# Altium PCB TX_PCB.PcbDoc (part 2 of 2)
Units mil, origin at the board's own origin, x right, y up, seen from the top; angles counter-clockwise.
Board outline 2335 x 2060 mil, 2 copper layers (Top Layer, Bottom Layer); 122 components, 95 nets, 483 pads, 219 vias.
Unrouted connection lines stored in the file: 1.
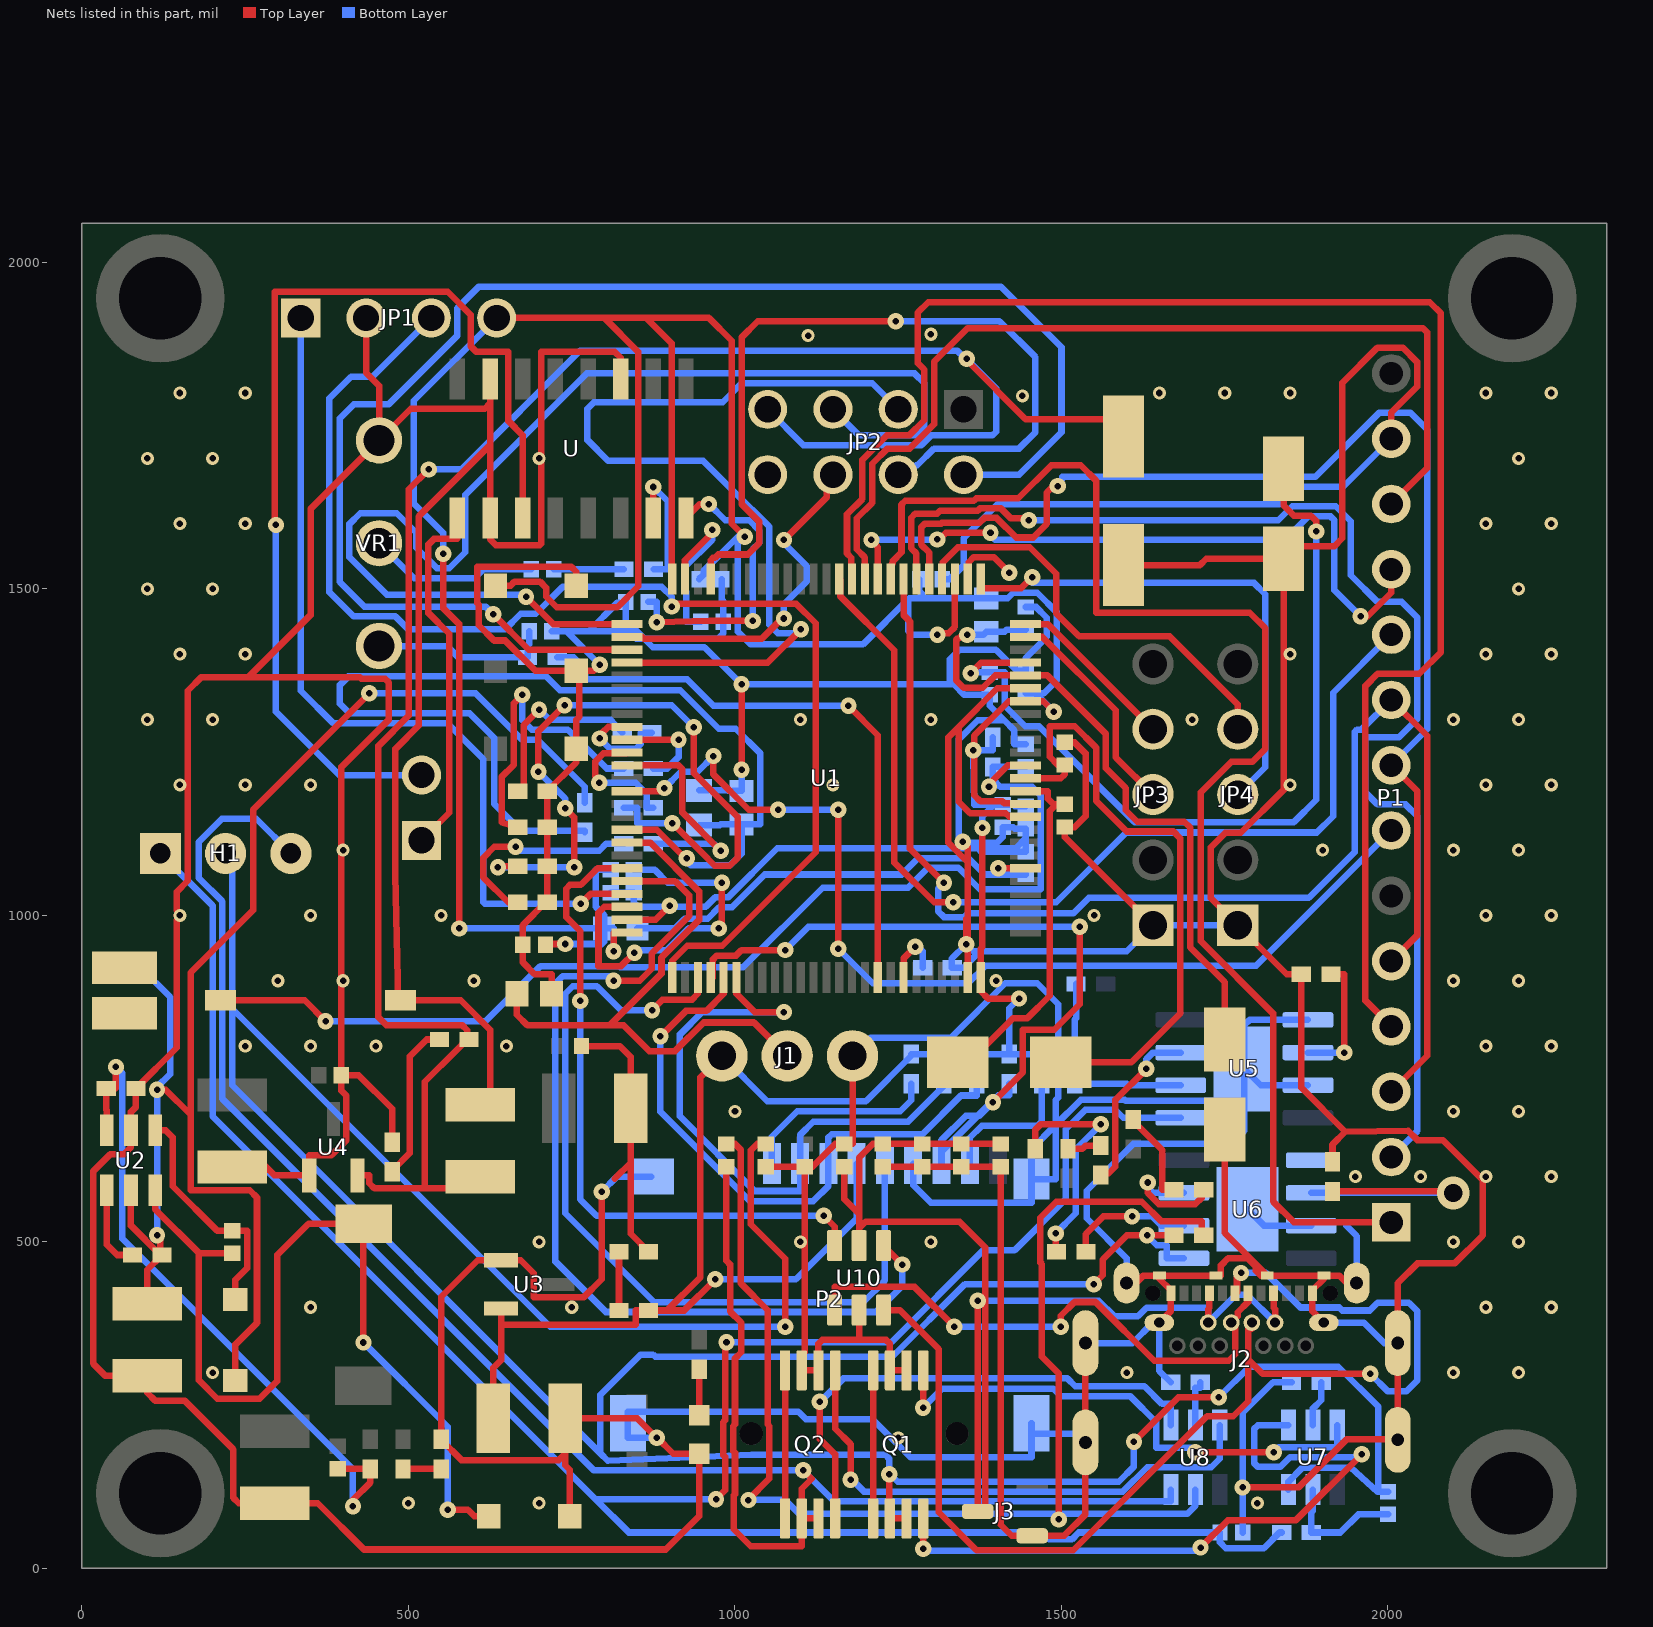
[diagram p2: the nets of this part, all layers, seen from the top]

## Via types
v1: diameter 25, hole 10, Top Layer to Bottom Layer, 130 vias
v2: diameter 20, hole 10, Top Layer to Bottom Layer, 86 vias
v3: diameter 70.87, hole 59.06, Top Layer to Bottom Layer, 2 vias
v4: diameter 50, hole 28, Top Layer to Bottom Layer, 1 vias

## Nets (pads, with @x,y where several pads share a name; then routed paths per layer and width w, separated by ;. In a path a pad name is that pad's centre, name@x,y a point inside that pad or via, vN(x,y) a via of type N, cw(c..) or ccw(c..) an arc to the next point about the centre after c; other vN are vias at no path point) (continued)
+5_USB_A: C34.1 C35.1 C36.1 C37.1 C42.2 J2.A4 J2.A9 J2.B4 J2.B9 J3.3 U10.5 | length 2013.9
  Top Layer w10: C42.2@1167.36,615.35 1167.36,565.64 1190,543 ; U10.5@1190,494.41 1190,521 ; J3.3@1371.54,87.4 J3.3@1372,87.4 ; v1(1372,410) J3.3@1372,87.4 ; C37.1@1407.09,650 C36.1@1346.81,650 C34.1@1286.54,650 C35.1@1226.26,650 1211,650 1190,629 1190,543 ; J2.B9@1724.65,376.5 1724.65,397 1726.61,398.97 J2.A4@1726.61,421.38 ; J2.A9@1825.04,421.38 1825.04,398.97 1827.01,397 J2.B4@1827.01,376.5 ; 1190,521 1190,543 ; 1190,521 1200,531 1344,531 1383,492 1383,87.4 J3.3@1372,87.4
  Bottom Layer w10: v1(1372,410) 1557,410 1581,386 1617,386 1630.29,399.29 1724.65,399.29 J2.B9@1724.65,376.5 1767.15,419 1784.5,419 J2.B4@1827.01,376.5
+8.4: C21.2 D1.1 pad.9 R7.2 R20.2 U2.5 | length 2453.6
  Top Layer w10: U2.5@75,579 75,525 R20.2@120,480 ; C21.2@100,405.12 100,457.36 R20.2@122.64,480 R20.2@120,480 ; v1(115,510) 120,505 R20.2@120,480 ; v1(115,733) 128,733 166.42,694.58 ; D1.1@235,287.99 235,343 268,376 268,568 257,579 166.42,579 166.42,694.58 ; v1(440,1340) 262,1162 262,1008 166.42,912.42 166.42,694.58
  Bottom Layer w10: pad.9@65,920 90,920 135,875 135,757.06 115,737.06 v1(115,510) ; v1(440,1340) 603.03,1340 674.03,1269 698,1269 770,1197 R7.2@770,1172.64
ADC_Pin: C29.2 R7.1 R15.2 U1.67 | length 1700.5
  Top Layer w10: U1.67@834.88,1131.26 880.11,1131.26 923.87,1087.5 v1(926.04,1087.5)
  Bottom Layer w10: R7.1@770,1127.36 770,1130 672,1130 631,1171 631,1272 593.44,1309.56 409.57,1309.56 395,1324.13 395,1353 408,1366 711,1366 732,1345 916,1345 975,1286 1001,1286 1039,1248 1039,1139.41 R15.2@1010,1139.41 ; v1(926.04,1087.5) 926.04,1082.72 931.9,1076.86 931.9,1076.5 992,1076.5 1010,1094.5 R15.2@1010,1139.41 ; C29.2@945,1138.43 977,1138.43 977.98,1139.41 R15.2@1010,1139.41
ADC_VR_ESC: C24.2 J1.2 U1.68 | length 911.5
  Top Layer w10: C24.2@665.92,880 665.92,848 682.42,831.5 808,831.5 ; U1.68@834.88,1111.58 870.14,1111.58 945,1036.72 945,992.96 887.48,935.44 887.48,910.98 808,831.5 ; J1.2@1080,785 1029,836 952.07,836 908.33,792.26 868.74,792.26 829.5,831.5 808,831.5
Audio_PWM: R8.2 U1.92 | length 920.6
  Top Layer w10: v1(1173.74,1321) 1218.74,1276 U1.92@1218.74,904.88
  Bottom Layer w10: R8.2@727.64,1395 753,1395 771,1377 771,1361.5 926.5,1361.5 967,1321 v1(1173.74,1321)
B+: C38.1 H1.1 R27.2 U5.5 | length 3719.2
  Top Layer w10: v1(971,106) 985,120 985,170.68 982.21,173.47 982.21,224.15 985,226.95 985,344.5 v1(987,346.5)
  Bottom Layer w10: H1.1@120,1095 200,1015 200,692.5 786.5,106 ; v1(971,106) 786.5,106 ; v1(987,346.5) 1239.5,346.5 1380,487 1428,487 1506.59,565.59 1506.59,672.48 1536.62,702.5 1582,702.5 1594.5,690 U5.5@1682.56,690 ; R27.2@1837.36,55 1834,55 1810,31 1751.68,31 1742.68,40 C38.1@1742.68,55 1526.5,55 1516,44.5 1481.5,44.5 1471,55 837.5,55 786.5,106
B-: C41.2 H1.3 Q2.2 Q2.3 U8.6 | length 3153.6
  Top Layer w10: C41.2@986.54,615.35 986.54,471.46 992.5,465.5 992.5,393.5 1009.5,376.5 1009.5,331 1000,321.5 1000,220.73 997.21,217.94 997.21,179.69 1000,176.89 1000,113.79 998.1,111.89 998.1,59.9 1024,34 1102.2,34 Q2.2@1102.2,76.61 ; v1(1104.3,150.5) 1117.5,137.3 1102.2,122 Q2.2@1102.2,76.61 ; Q2.3@1127.8,76.61 Q2.2@1102.2,76.61
  Bottom Layer w10: H1.3@320,1095 267,1148 214.32,1148 178.5,1112.19 178.5,1057.71 215,1021.21 215,719 784,150 1031.5,150 1032,150.5 v1(1104.3,150.5) 1152.16,102.64 1667.64,102.64 U8.6@1667.64,120.59
B_COM: C39.2 C40.1 H1.2 Q1.2 Q1.3 R31.2 U6.5 U7.6 | length 5453
  Top Layer w10: C40.1@1046.81,650 1034.21,650 1024.21,640 1024.21,527 1077,474.21 v1(1077,370) ; v1(1236,144) 1236,77.82 Q1.2@1237.2,76.61 Q1.3@1262.8,76.61 ; v1(1549.39,435.39) 1563,449 1563,473 1600,510 v1(1631,510) R31.2@1672.36,510 ; v1(1611,194) 1679,262 v1(1741,262)
  Bottom Layer w10: H1.2@220,1095 230,1085 230,857 ; v1(1077,370) 717,370 230,857 ; v1(1549.39,435.39) 1352.39,435.39 1241,324 877.82,324 874.32,327.5 855.68,327.5 794,265.82 794,176 ; v1(1611,194) 1611,156 1587.64,132.64 1249.36,132.64 1237.99,144 v1(1236,144) 1236,168.14 1230.14,174 1035,174 1025.5,174 805,165 794,176 ; v1(1631,510) 1646,495 1661,495 1661,475 U6.5@1687.56,475 ; v1(1741,262) 1788,309 1924,309 1985.32,247.69 1985.32,118.14 1984.5,117.32 ; U7.6@1847.6,120.59 1847.6,132.79 1869.21,154.41 1938.16,154.41 1943.1,154.31 1984.5,117.32 ; C39.2@2000,117.32 1984.5,117.32 ; 230,857 230,740 794,176
BOOT0: R6.2 U1.94 | length 93.8
  Top Layer w10: U1.94@1258.11,904.88 1258.11,934.11 v1(1276.18,952.18)
  Bottom Layer w10: v1(1276.18,952.18) 1280,952.18 1287.36,944.82 R6.2@1287.36,920
CHRG_LED: R28.1 U5.7 | length 270.7
  Top Layer w10: R28.1@1560,602.36 1560,605 1572.5,605 1582.5,615 1582.5,717.5 v1(1630,765)
  Bottom Layer w10: v1(1630,765) 1630,780 1640,790 U5.7@1682.56,790
CHRG_LED_1: R32.1 U6.7 | length 191.7
  Top Layer w10: v1(1632,591) 1632,575 1649,558 1705,558 1715,568 1715,580 R32.1@1717.64,580
  Bottom Layer w10: v1(1632,591) 1632,583 1640,575 U6.7@1687.56,575
CLK_SD: P2.5 U1.78 | length 1333
  Top Layer w10: v1(873,855) 889,871 934.15,871 943.15,880 U1.78@943.15,904.88
  Bottom Layer w10: v1(873,855) 825,855 788.5,891.5 751.5,891.5 740,880 740,544 876.31,407.69 1196.33,407.69 1229.65,441 P2.5@1229.65,619.84
CS_SD: P2.2 R18.1 U1.81 | length 980.2
  Top Layer w10: U1.81@1002.2,904.88 1002.2,880 1030.2,852 v1(1075,852)
  Bottom Layer w10: v1(1075,852) 950,852 915.63,817.63 915.63,692.37 1030,578 1099.72,578 P2.2@1099.72,619.84 1099.72,663.72 1120,684 1265,684 1320,739 R18.1@1320,742.36
DISPL_CS: P1.12 U1.35 | length 1471.8
  Top Layer w10: U1.35@1199.06,1515.12 1199.06,1548.06 1186.51,1560.6 1186.51,1608.07 1210.08,1631.64 1210.08,1691.54 1233.54,1715 1267.67,1715 1304.92,1752.25 1304.92,1847.92 1356.53,1899.53 2053.21,1899.53 2060,1892.74 2060,1685 P1.12@2005,1630
DISPL_DC: P1.10 U1.37 | length 1535.9
  Top Layer w10: U1.37@1159.69,1515.12 1160.99,1513.82 1160.99,1489.01 1244,1406 1244,1081 1305,1020 v1(1334,1020)
  Bottom Layer w10: v1(1334,1020) 1492,1020 1599,1127 1891,1127 1916,1152 1916,1341 P1.10@2005,1430
DISPL_LED: P1.7 U1.64 | length 1574.6
  Top Layer w10: U1.64@834.88,1190.32 887.32,1190.32 v1(892,1195) ; v1(967,1244) 967,1216 1021,1162 v1(1066,1162) ; v1(1158,949) v1(1158,1162)
  Bottom Layer w10: v1(892,1195) 917,1220 943,1220 v1(967,1244) ; v1(1066,1162) v1(1158,1162) ; v1(1158,949) 1211,896 1357,896 1384,923 1798,923 P1.7@2005,1130
DISPL_MOSI: P1.3 P1.9 U1.32 | length 2126.7
  Top Layer w10: U1.32@1258.11,1515.12 1258.11,1459.89 1268,1450 1268,1102 v1(1320,1050) ; P1.3@2005,730 2060,785 2060,1275 P1.9@2005,1330
  Bottom Layer w10: v1(1320,1050) 1311,1041 1311,1006.5 1320,997.5 1351.5,997.5 1357,1003 1518,1003 1542,1027 1879,1027 1949,1097 1949,1280.91 1952.62,1284.53 1959.53,1284.53 P1.9@2005,1330
DISPL_RST: P1.11 U1.34 | length 1055.6
  Top Layer w10: v1@1209.01,1569.92 1212.88,1569.92 1218.74,1564.06 U1.34@1218.74,1515.12 ; v1(1309.69,1575.72) 1312.68,1575.72 1323.05,1586.09 1337.26,1586.09 1337.41,1586.24 v1(1391.27,1586.24) ; v1(1958,1458) 1969,1458 2005,1494 P1.11@2005,1530
  Bottom Layer w10: v1@1214.09,1575 1214.45,1575.36 1309.33,1575.36 v1(1309.69,1575.72) ; v1(1391.27,1586.24) 1391.27,1582.18 1398.45,1575 1842,1575 1878,1611 1912,1611 1918,1605 1918,1498 v1(1958,1458)
  other v1: 1209.01,1575
DISPL_SCK: P1.5 P1.8 U1.30 | length 1869.7
  Top Layer w10: U1.30@1297.48,1515.12 1297.48,1555.7 1285,1568.18 1285,1594.14 1290.86,1600 1315.75,1600 1316.99,1601.24 1374.45,1601.24 1381.95,1608.74 1400.58,1608.74 1430.58,1578.74 1456.77,1578.74 1477.5,1599.47 1477.5,1647.5 1487.5,1657.5 v1(1494.32,1657.5) ; P1.5@2005,930 2045,970 2045,1190 P1.8@2005,1230
  Bottom Layer w10: v1(1494.32,1657.5) 1494.32,1661.56 1501.5,1668.74 1501.5,1671.5 1888.5,1671.5 1987,1770 2034,1770 2060,1744 2060,1285 P1.8@2005,1230
GND: C1.1 C2.1 C3.1 C4.1 C5.1 C6.1 C7.2 C8.1 C9.1 C10.1 C11.1 C12.1 C13.1 C14.1 C15.1 C17.1 C18.1 C21.1 C22.1 C23.1 C24.1 C25.2 C26.1 C27.2 C28.1 C29.1 C30.2 C31.1 C32.1 C33.1 C34.2 C35.2 C36.2 C37.2 C38.2 C40.2 C42.1 C43.2 D2.1 D3.2 D4.1 D5.2 D8.1 D9.1 D10.2 D11.2 D12.2 D13.2 D14.2 D15.2 J1.1 J2.A1 J2.A12 J2.B1 J2.B12 J2.S J3.1 JP1.2 JP2.5 JP3.1 JP4.1 P1.13 P2.6 P2.G1 P2.G2 P2.G3 P2.G4 pad.10 Q1.6 Q1.7 Q2.6 Q2.7 R6.1 R10.1 R15.1 R22.1 R25.1 R26.2 R30.2 S2.1 U1.10 U1.20 U1.27 U1.74 U1.99 U2.2 U3.1 U4.1 U5.1 U5.3 U5.9 U6.1 U6.3 U6.9 U10.2 U.2 U.11 U.15 VR1.2 | length 25006.7
  Top Layer w10: C31.1@230,614.76 282,614.76 294.76,602 U4.1@348,602 348,633 382,633 405,656 405,724 397.32,731.68 C32.1@397.32,755 ; v2@397.32,900 C32.1@397.32,755 ; JP1.2@435,1915 435,1831 455,1811 VR1.2@455,1727.48 ; D15.2@475,652.64 475,704 424,755 C32.1@397.32,755 ; C33.1@610,710.12 625,725.12 625,825 580,870 S2.1@487.8,870 484,870 480,1062 480,1255 515.5,1290.5 515.5,1610.77 625,1720.27 ; U.15@625,1821.3 625,1784 ; C24.1@719.07,877.93 C24.1@719.07,880 719.07,910 693.18,910 675.18,928 C13.1@675.18,955 675.18,985.18 710,1020 D13.2@712.64,1020 D12.2@712.64,1075 D11.2@712.64,1135 D10.2@712.64,1190 757.01,1234.37 D9.1@757.01,1255 757.01,1299.5 761.5,1303.99 761.5,1361.3 757.01,1361.3 D8.1@757.01,1375 ; D2.1@747.01,80 747.01,151 740.12,157.89 740.12,176 ; D4.1@757.01,1505 757.01,1526.2 749.5,1533.7 605.27,1533.7 605.27,1478.23 607.5,1476 607.5,1444.5 631,1421 648,1421 694,1375 D8.1@757.01,1375 ; C26.1@765,800 823.47,800 840.24,783.24 C23.1@840.24,705 840.24,621.24 ; v1(793,1384) 784,1375 D8.1@757.01,1375 ; v1(796,577) 796,443 768,415 692,415 692,452 672,472 U3.1@642,472 606,472 550,416 D3.2@550,197.64 550,197 581,166 730.12,166 740.12,176 ; 816,597 840.24,621.24 ; U.11@825,1821.3 825,1854 816,1863 703,1863 703,1569 701,1567 634,1567 625,1576 U.2@625,1608.7 625,1720.27 ; U1.74@834.88,993.47 878.47,993.47 v1(900,1015) ; D14.2@867.64,485 840.24,512.4 840.24,621.24 ; v1(880,200) 850,230 C28.1@740.12,230 740.12,176 ; v1@880.5,200.5 905.53,175.47 D5.2@945,175.47 945,80 894,29 431.88,29 361,99.88 C22.1@295,99.88 240,99.88 232,107.88 232,182 157,257 112,257 100,269 C21.1@100,294.88 36,294.88 17,313.88 17,608 43,634 64,634 75,645 U2.2@75,671 75,699 82.64,706.64 R22.1@82.64,735 145,797.36 145,992.29 148.09,995.38 148.09,997.29 145.38,1000 148.09,1002.71 148.09,1004.62 145,1007.71 145,1036 162,1053 162,1344 183,1365 255,1365 ; v1(1010,1223) v1(1010,1354) ; C40.2@1046.81,615.35 C43.2@1107,615.35 ; J1.1@1180,785 1180,650 C42.1@1167.36,650 1153.65,650 1119,615.35 C43.2@1107.09,615.35 C43.2@1107,615.35 ; U10.2@1190,395.59 1190,350 1189.84,349.84 ; C35.2@1226.26,615.36 C34.2@1286.54,615.36 C36.2@1346.81,615.36 C37.2@1407.09,615.36 1407.09,66.91 1424,50 J3.1@1455,50 1504,50 1536.65,82.65 J2.S@1536.65,193.03 J2.S@1536.65,345 ; Q1.6@1262.8,303.39 Q1.7@1237.2,303.39 1237.2,343.99 1231.35,349.84 1189.84,349.84 ; v1(1349,1113) 1356.5,1105.5 1356.5,1081.6 ; U1.99@1356.54,904.88 v1@1356.54,953.46 ; U1.27@1356.54,1515.12 1357.84,1516.42 1357.84,1540.8 1365.78,1548.74 1396.26,1548.74 v1(1420,1525) ; U1.10@1445.12,1150.95 1420.05,1150.95 1414.43,1156.57 1360,1156.57 1342.5,1174.07 1342.5,1288.5 ; U1.20@1445.12,1347.8 1401.8,1347.8 1342.5,1288.5 ; C4.1@1505,1265 1520,1265 1536.9,1248.1 1536.9,1152 1520.26,1135.35 C5.1@1505,1135.35 1505,1120 JP3.1@1640,985 ; C25.2@1595,1536.57 1712,1536.57 1721.53,1546.1 C30.2@1840,1546.1 ; J2.S@1599.65,437.13 1614.13,437.13 1625.54,448.54 J2.S@1649.84,448.54 ; J2.B12@1649.84,376.5 1667.56,394.21 J2.A1@1667.56,421.38 1667.56,426 1649.84,443.72 J2.S@1649.84,448.54 ; C27.2@1750,672.2 1750,513.74 J2.S@1815.2,448.54 ; v1(1777.32,124) 1863,124 1936.5,197.5 2014.47,197.5 J2.S@2015,196.97 J2.S@2015,345 2015,437 2045,467 2102,467 2145,510 2145,595 2084,656 2045,656 2031,670 1934.68,668.68 ; J2.B1@1901.81,376.5 1884.09,394.21 J2.A12@1884.09,421.38 1884.09,426 1901.81,443.72 J2.S@1901.81,448.54 ; R10.1@1915,622.64 1915,649 1934.68,668.68 ; J2.S@1952.01,437.13 1936.87,437.13 1925.46,448.54 J2.S@1901.81,448.54 ; P1.13@2005,1730 2005,1770 2044.53,1809.53 2044.53,1847.66 2022.66,1869.53 1984,1869.53 1930,1815.53 1930,1577.5 1918,1565.5 1840,1565.5 C30.2@1840,1546.1 ; 255,1365 350,1460 350,1622.48 VR1.2@455,1727.48 ; 255,1365 425,1365 427.5,1362.5 464.14,1362.5 470,1356.64 470,1300 397.32,1227.32 C32.1@397.32,755 ; VR1.2@455,1727.48 503.52,1776 617,1776 625,1784 ; 625,1720.27 625,1784 ; C43.2@1107,615.35 1107,330.8 1102.2,326 Q2.7@1102.2,303.39 Q2.6@1127.8,303.39 1127.8,343.99 1133.65,349.84 1189.84,349.84 ; 1342.5,1288.5 1326.54,1272.54 1326.54,1111.57 1356.5,1081.6 ; 1356.5,1081.6 1356.5,997.5 1354,995 v1(1354,956) v1@1356.54,953.46 ; 1356.5,1081.6 1356.54,1081.57 v1@1356.54,953.46 ; J2.S@1649.84,448.54 J2.S@1736.46,448.54 1744.15,448.54 1744.15,464 1755.15,475 1784.32,475 1797.5,461.82 1797.5,456 1804.96,448.54 J2.S@1815.2,448.54 ; J2.S@1815.2,448.54 J2.S@1901.81,448.54 ; C30.2@1840,1546.1 1840,1192 1774.5,1126.5 1751,1126.5 1728.5,1104 1728.5,1026.5 JP4.1@1770,985 1845,910 R25.1@1867.36,910 1867.36,736 1934.68,668.68
  Bottom Layer w10: C17.1@719.64,1435 742,1435 ; v1(793,1384) 742,1435 ; v1(796,577) 819.16,600.16 P2.G4@871.38,600.16 ; C11.1@810,1035 C2.1@845,1035 845,1020 851.5,1013.5 955.47,1013.5 969.47,1027.5 989.32,1027.5 1064.7,1102.88 1358.12,1102.88 ; C18.1@832.68,1480 C18.1@832.68,1479 ; v1(880,200) 835.94,200 P2.G3@835.94,222.21 835.94,240 1097.13,240 1108.39,228.74 1210.26,228.74 1269,170 1454.06,170 P2.G2@1454.06,206 ; C29.1@945,1191.57 988.97,1191.57 989.95,1190.59 R15.1@1010,1190.59 v1(1010,1223) ; C8.1@979.65,1515 979.65,1483.68 982.32,1481 C1.1@982.32,1450 982.32,1432 974.32,1424 861,1424 ; J1.1@1180,785 1208,813 1331,813 1414,896 1463,896 1495,864 1495,721 1491,717 1491,679 ; P2.6@1272.95,619.84 1272.95,587.05 1300,560 1454.06,560 P2.G1@1454.06,596.22 ; C14.1@1317.17,1515.12 1329.12,1515.12 1350,1536 1350,1577.53 1402.47,1630 1833.75,1630 1860.25,1656.5 1931.5,1656.5 P1.13@2005,1730 ; v1(1349,1113) 1349,1112 1358.12,1102.88 ; C3.1@1445,1262.32 1428,1262.32 1428,1283 1412.2,1298.8 ; C6.1@1445,1472.32 1461.15,1472.32 1477.47,1456 1477.47,1426.47 1445,1394 C12.1@1445,1374.65 1432,1374.65 1399.65,1407 1344,1407 1329,1392 1329,1360 1335,1354 ; P2.G2@1454.06,222.21 P2.G2@1454.06,206 ; J2.S@1536.65,193.03 1536.65,206 P2.G2@1454.06,206 ; J2.S@1536.65,345 1608.5,345 1640,376.5 J2.B12@1649.84,376.5 1649.84,302.52 R30.2@1667.36,285 ; J2.S@1599.65,437.13 1599.65,475 1538.5,536.15 1538.5,578.5 1610,650 1760,650 1780,670 U5.9@1780,716 ; JP4.1@1770,985 JP3.1@1640,985 1600,945 1365,945 ; C38.2@1777.32,55 v1(1777.32,124) 1777.32,238.32 1824,285 R26.2@1852.36,285 ; U6.9@1785,550 1810,525 U6.3@1882.44,525 ; U5.3@1877.44,740 1805,740 U5.9@1780,765 ; U5.1@1877.44,840 1788,840 1780,832 U5.9@1780,765 ; J2.B1@1901.81,376.5 1963,376.5 1994.5,345 J2.S@2015,345 ; 1936,525 1952.01,508.99 J2.S@1952.01,437.13 ; 742,1435 776,1435 ; 776,1435 837.68,1435 ; 776,1435 820,1479 C18.1@832.68,1479 ; C18.1@832.68,1479 832.68,1440 837.68,1435 ; 837.68,1435 850,1435 861,1424 ; 837.68,1435 848.68,1424 861,1424 ; 861,1424 874.21,1410.79 953.21,1410.79 v1(1010,1354) 1335,1354 ; 1335,1354 1351.32,1337.68 C7.2@1390,1337.68 1390,1321 1412.2,1298.8 ; 1358.12,1102.88 1372.12,1102.88 ; 1365,945 1370,940 1350,920 R6.1@1332.64,920 1332,920 1332,934 v1(1354,956) 1365,945 ; 1372.12,1102.88 1429.88,1102.88 1445,1118 ; 1372.12,1102.88 1377.68,1097.32 C15.1@1445,1097.32 1445,1118 ; 1412.2,1298.8 1371.8,1298.8 1342.5,1269.5 1342.5,1120.71 1351.71,1111.5 1401.5,1111.5 1410,1120 C9.1@1410,1135 1426,1135 1428.32,1132.68 C10.1@1445,1132.68 1445,1118 ; P2.G1@1454.06,596.22 1491,596.22 1491,679 ; P2.G1@1454.06,596.22 1454.06,642.06 1491,679 ; 1491,679 1529.5,717.5 1597,717.5 1598.5,716 U5.9@1780,716 ; U5.9@1780,716 U5.9@1780,765
  other v2: 500,100 700,100 1800,100 1250,200 200,300 1600,300 2100,300 2200,300 350,400 750,400 2150,400 2250,400 700,500 1100,500 1300,500 2100,500 2200,500 1950,600 2050,600 2150,600 2250,600 1000,700 2100,700 2200,700 250,800 350,800 450,800 650,800 2150,800 2250,800 300,900 400,900 600,900 1400,900 2100,900 2200,900 150,1000 350,1000 550,1000 1550,1000 2150,1000 2250,1000 400,1100 1900,1100 2100,1100 2200,1100 150,1200 250,1200 350,1200 1150,1200 1850,1200 2150,1200 2250,1200 100,1300 200,1300 1100,1300 1300,1300 1700,1300 2100,1300 2200,1300 150,1400 250,1400 1850,1400 2150,1400 2250,1400 100,1500 200,1500 2200,1500 150,1600 250,1600 2150,1600 2250,1600 100,1700 200,1700 700,1700 2200,1700 1440,1795.72 150,1800 250,1800 1650,1800 1750,1800 1850,1800 2150,1800 2250,1800 1112.07,1887.93 1300,1890
JOY1_X: JP3.3 U1.24 | length 337.2
  Top Layer w10: U1.24@1445.12,1426.54 1470.7,1426.54 1583,1314.24 1583,1242 JP3.3@1640,1185
JOY1_Y: JP3.4 U1.25 | length 261.7
  Top Layer w10: U1.25@1445.12,1446.22 1478.78,1446.22 JP3.4@1640,1285
JOY2_X: JP4.3 U1.26 | length 797.3
  Top Layer w10: U1.26@1376.22,1515.12 1376.22,1501 1438,1501 v1(1455,1518)
  Bottom Layer w10: v1(1455,1518) 1455,1509.13 1794.87,1509.13 1812,1492 1812,1227 JP4.3@1770,1185
JOY2_Y: JP4.4 U1.29 | length 660.5
  Top Layer w10: U1.29@1317.17,1515.12 1318.47,1516.42 1318.47,1540.8 1341.41,1563.74 1451.26,1563.74 1491.85,1523.15 1491.85,1462.52 1526.87,1427.5 1665.5,1427.5 1770,1323 JP4.4@1770,1285
LED1: R1.1 U1.59 | length 158.7
  Top Layer w10: v1(793,1271) 797,1275 797,1280 805.74,1288.74 U1.59@834.88,1288.74
  Bottom Layer w10: v1(793,1271) 809,1255 848,1255 856,1263 856,1280 R1.1@872.64,1280
LED2: R2.1 U1.60 | length 151
  Top Layer w10: U1.60@834.88,1269.06 v1(913.56,1269.06)
  Bottom Layer w10: R2.1@875,1225 896,1225 913.56,1242.56 v1(913.56,1269.06)
LED3: R3.1 U1.61 | length 200.9
  Top Layer w10: v1(792,1203) 792,1207.06 785.98,1213.08 785.98,1235.9 798.15,1248.07 833.58,1248.07 U1.61@834.88,1249.37
  Bottom Layer w10: v1(792,1203) 848,1203 865,1186 865,1165 R3.1@875,1165
LED4: R5.1 U1.62 | length 343.6
  Top Layer w10: U1.62@834.88,1229.69 913.6,1229.69 919.46,1223.83 919.46,1157.54 v1(978,1099)
  Bottom Layer w10: R5.1@875,1110 967,1110 v1(978,1099)
MISO_SD: P2.7 R12.1 U1.79 | length 1261.5
  Top Layer w10: U1.79@962.83,904.88 966.22,904.88 966.22,932.65 972.08,938.5 1001.54,938.5 1010.03,947 v1(1077,947) ; v1(1395,714) 1441,760 1441,825 1489,825 1528,864 v1(1528,982.5)
  Bottom Layer w10: v1(1077,947) 1112.5,982.5 v1(1528,982.5) ; P2.7@1316.26,619.84 P2.7@1316.26,638 ; v1(1395,714) 1374,693 1371.26,693 ; R12.1@1420,742.36 1420,724.74 1403,724.74 1371.26,693 ; P2.7@1316.26,638 1371.26,693 ; P2.7@1316.26,638 1316.26,656 1353.26,693 1371.26,693
MOSI_SD: P2.3 R11.1 U1.80 | length 933.7
  Top Layer w10: v1(885.83,814.76) 924.84,853.77 956.29,853.77 982.52,880 U1.80@982.52,904.88
  Bottom Layer w10: v1(885.83,814.76) 885.83,699.17 1022.5,562.5 1120,562.5 1143.03,585.53 P2.3@1143.03,619.84 1143.03,660 1148.03,665 1286.96,665 1346.18,724.21 1370,724.21 R11.1@1370,742.36
NetC16_1: C16.1 VR1.0 | length 260.4
  Bottom Layer w10: VR1.0@455,1570 508.5,1516.5 601.51,1516.5 615.01,1530 C16.1@687.68,1530
NetC16_2: C16.2 R9.1 | length 107.7
  Bottom Layer w10: C16.2@722.32,1530 R9.1@830,1530
NetC17_2: C17.2 R8.1 VR1.1 | length 275.7
  Bottom Layer w10: VR1.1@455,1412.52 559,1412.52 576.52,1395 R8.1@682.36,1395 682.36,1413 685,1415.64 C17.2@685,1435
NetC18_2: C18.2 U.8 | length 471.7
  Top Layer w10: v1(880,1449) 962,1451 v1(1027,1451) ; U.8@925,1608.7 925,1609 946,1630 v1(960,1630)
  Bottom Layer w10: C18.2@867.32,1480 880,1480 v1(880,1449) ; v1(960,1630) 984.92,1605.08 1021.74,1605.08 1037.5,1589.32 1037.5,1570.68 1027,1560.18 v1(1027,1451)
NetC19_1: C19.1 R19.1 R22.2 U2.3 | length 1053.8
  Top Layer w10: U2.3@38,671 38,702 37.36,702.64 R22.2@37.36,735 52,735 v1(52,768) ; C19.1@391.66,152.67 416,152.67 416.31,152.36 R19.1@441.66,152.36 441.66,131.66 415,105 v1(415,95)
  Bottom Layer w10: v1(52,768) 62,758 62,505 415,152 v1(415,95)
NetC20_1: C20.1 D2.2 L1.1 U2.6 | length 1416.4
  Top Layer w10: U2.6@112,579 112,550 179,483 179,482.68 ; C20.1@230,482.68 179,482.68 ; v1(431,346) L1.1@431,528 ; L1.1@431.42,528 L1.1@431,528 ; v1(560,90) 591,90 601,80 D2.2@622.99,80 ; 179,482.68 179,288 207,260 272,260 299,287 299,480 347,528 L1.1@431,528
  Bottom Layer w10: v1(431,346) 560,217 v1(560,90)
NetC20_2: C20.2 D1.2 U2.1 | length 361.2
  Top Layer w10: U2.1@112,671 128,671 139,660 139,585.2 206.88,517.32 C20.2@230,517.32 253,517.32 253,460 235,442 D1.2@235,412.01
NetC39_1: C39.1 R27.1 U7.5 | length 195.4
  Bottom Layer w10: U7.5@1885,120.59 1885,88.36 1882.64,86 R27.1@1882.64,55 1927,55 1954.68,82.68 C39.1@2000,82.68
NetC41_1: C41.1 R31.1 U8.5 | length 2096.5
  Top Layer w10: C41.1@986.54,650 1000,650 1009.14,640.86 1009.14,436.36 1050,395.5 1050,220.58 1052.64,217.94 1052.64,137.64 1020.6,105.6 v1(1020.6,104.74) ; v1(1496,75) 1496,298 1470,324 1470,466 1467.6,468.4 1467.6,537.06 1492.03,561.5 1623,561.5 1652.5,532 1715,532 1715,510 R31.1@1717.64,510
  Bottom Layer w10: v1(1020.6,104.74) 1020.86,105 1077,105 1098.5,83.5 1496,83.5 1504,83.5 1692.54,83.5 1705.04,96 U8.5@1705.04,120.59 ; v1(1496,75) v1@1504,83
NetD3_1: D3.1 R21.1 | length 58.3
  Top Layer w10: R21.1@491.66,152.36 520,152.36 D3.1@550,152.36
NetD5_1: D5.1 R36.1 | length 70.5
  Top Layer w10: D5.1@945,234.53 R36.1@945,305
NetD10_1: D10.1 R1.2 | length 286.2
  Top Layer w10: D10.1@667.36,1190 676.42,1190 676.42,1291.42 v1(700,1315)
  Bottom Layer w10: v1(700,1315) 701,1315 716.5,1299.5 809.5,1299.5 R1.2@827.36,1280
NetD11_1: D11.1 R2.2 | length 459
  Top Layer w10: D11.1@667.36,1135 642.6,1142.4 642.6,1212 661.42,1230.82 661.42,1324.84 v1(674.29,1337.71)
  Bottom Layer w10: v1(674.29,1337.71) 674.29,1299.21 689,1284.5 744.09,1284.5 803.59,1225 R2.2@829.72,1225
NetD12_1: D12.1 R3.2 | length 1105.2
  Top Layer w10: v1(637,1074) 638,1075 D12.1@667.36,1075 ; v1(699,1220) 699,1282 v1(739,1322) ; v1(740,1164) 754,1150 v1(754,1074) ; v1(904,1141) 904.36,1141 948.54,1096.82 948.54,1096.64 969.18,1076 992,1076 1004,1088 1004,1151 937,1218 v1(937,1288)
  Bottom Layer w10: v1(637,1074) v1(754,1074) ; v1(699,1220) 740,1179 v1(740,1164) ; v1(739,1322) 903,1322 v1(937,1288) ; R3.2@829.72,1165 850,1165 850,1141 v1(904,1141)
NetD13_1: D13.1 R5.2 | length 327.9
  Top Layer w10: v1(664,1105) 631.5,1105 614.5,1088 614.5,1058.1 652.6,1020 D13.1@667.36,1020
  Bottom Layer w10: v1(664,1105) 670,1099 792,1099 803,1110 R5.2@829.72,1110
NetD14_1: D14.1 R23.1 | length 90
  Top Layer w10: R23.1@822.36,395 D14.1@822.36,485
NetD15_1: D15.1 R24.1 | length 244
  Top Layer w10: D15.1@475,607.36 475,609 502,636 502,784 528,810 R24.1@547.36,810
NetD16_2: D16.2 R29.1 | length 108.3
  Bottom Layer w10: R29.1@1520,787.64 1520,840 1522.36,842.36 D16.2@1522.36,895
NetD17_2: D17.2 R28.2 | length 52.1
  Top Layer w10: D17.2@1510,642.64 1532,642.64 1537,647.64 R28.2@1560,647.64
NetD18_2: D18.2 R32.2 | length 143.9
  Top Layer w10: D18.2@1610,687.64 1610,685 1654.5,640.5 1654.5,580 R32.2@1672.36,580
NetD19_2: D19.2 R33.1 | length 357.6
  Top Layer w10: D19.2@1460,642.64 1460,672 1468,680 v1(1560,680) ; v1(1491,513) 1491,485 R33.1@1492.36,485
  Bottom Layer w10: v1(1491,513) 1522,544 1522,642 v1(1560,680)
NetJ2_A6: J2.A6 J2.B6 U10.3 | length 1821.6
  Top Layer w10: U10.3@1227.4,395.59 1252.41,395.59 1312,336 1312,86 1370,28 1518,28 1723,233 1763,233 1786,256 1786,320 ; J2.A6@1765.98,421.38 1767,421.38 1768.78,423.16 1768.78,446.28 v1(1775,452.5) ; v1(1973,298) 1808,298 1786,320 ; 1786,320 J2.B6@1786,367 ; J2.B6@1786,367 1791.57,367 J2.B6@1791.57,376.5 1786,370.92 J2.B6@1786,367
  Bottom Layer w10: v1(1775,452.5) 1813.07,452.5 1866,399.57 1925.43,399.57 1930,395 1972,395 1984,407 2032,407 2045,394 2045,288 2028,271 2000,271 v1(1973,298)
NetJ2_A7: J2.A7 J2.B7 U10.1 | length 847.6
  Top Layer w10: U10.1@1152.6,395.59 1152.6,431 1275,431 v1(1336,370) ; v1(1499,370) 1499,387 1520,408 1552,408 1642,318 1756,318 1766,328 1766,370.57 J2.B7@1760.08,376.5 1770,386.42 1770,392.33 1785.67,408 J2.A7@1785.67,421.38
  Bottom Layer w10: v1(1336,370) v1(1499,370)
NetJP5_1: JP5.1 U.1 | length 563.9
  Top Layer w10: JP5.1@520,1115 562.3,1157.3 562.3,1431.3 530.5,1463.09 530.5,1568 539,1576.5 575,1576.5 U.1@575,1608.7
NetJP5_2: JP5.2 U.3 | length 1594.6
  Top Layer w10: v1(297,1598) 295,1600 295,1955 560,1955 595,1920 595,1872 604,1863 653,1863 653,1757 675,1735 U.3@675,1608.7
  Bottom Layer w10: v1(297,1598) 297,1312 394,1215 JP5.2@520,1215
NetP2_1: P2.1 R17.1 | length 303.3
  Bottom Layer w10: P2.1@1056.42,619.84 1056.42,661 1095.42,700 1253,700 1270,717 R17.1@1270,742.36
NetP2_8: P2.8 R13.1 | length 218.4
  Bottom Layer w10: P2.8@1359.57,619.84 1359.57,659.42 1377.75,677.6 1463.39,677.6 1470,684.21 R13.1@1470,742.36
NetQ1_1: Q1.1 Q1.8 | length 226.8
  Top Layer w10: Q1.1@1211.61,76.61 Q1.8@1211.61,303.39
NetQ1_4: Q1.4 U7.1 | length 1063.5
  Top Layer w10: v1(1288.39,30) Q1.4@1288.39,76.61 ; v1(1713,32) 1754.5,73.5 1858.5,73.5 v1(1960,175)
  Bottom Layer w10: v1(1288.39,30) 1291.39,27 1708,27 v1(1713,32) ; U7.1@1847.6,219.41 1800.86,219.41 1795,213.55 1795,161.36 1800.86,155.5 1835.1,155.5 1850.19,170.59 1955.59,170.59 v1(1960,175)
NetQ1_5: Q1.5 U7.3 | length 804.4
  Top Layer w10: v1(1288,246) 1288.39,246.39 Q1.5@1288.39,303.39 ; v1(1705,178) v1(1825,178)
  Bottom Layer w10: v1(1288,246) 1317.51,275.51 1487.49,275.51 1499,264 1605,264 1645,224 1645,185 1698,185 v1(1705,178) ; v1(1825,178) 1832.59,185.59 1922.4,185.59 U7.3@1922.4,219.41
NetQ2_1: Q2.1 Q2.8 | length 226.8
  Top Layer w10: Q2.1@1076.61,76.61 Q2.8@1076.61,303.39
NetQ2_4: Q2.4 U8.1 | length 789.4
  Top Layer w10: v1(1130,255) 1130,198 1153.39,174.61 Q2.4@1153.39,76.61
  Bottom Layer w10: v1(1130,255) 1166,291 1509,291 1521,279 1627,279 1654,252 1667.64,252 U8.1@1667.64,219.41
NetQ2_5: Q2.5 U8.3 | length 822.5
  Top Layer w10: Q2.5@1153.39,303.39 1153.39,214 1177,190.39 v1(1177,136)
  Bottom Layer w10: v1(1177,136) 1179.16,136 1197.53,117.64 1593.85,117.64 1631.21,155 1729.44,155 1742.44,168 U8.3@1742.44,219.41
NetR9_2: R9.2 U.7 | length 204.3
  Top Layer w10: U.7@875,1608.7 v1(875,1656.09)
  Bottom Layer w10: v1(875,1656.09) 897,1634.09 897,1530 R9.2@875.28,1530
NetR10_2: R10.2 U6.2 | length 403.5
  Top Layer w10: R10.2@1915,577.36 2097.64,577.36 v4(2100,575)
  Bottom Layer w10: U6.2@1882.44,575 v4(2100,575)
NetR20_1: R20.1 U2.4 | length 129
  Top Layer w10: U2.4@38,579 38,496 54,480 R20.1@77.36,480
NetR25_2: R25.2 U5.2 | length 195.9
  Top Layer w10: R25.2@1912.64,910 1933,910 v1(1933,790)
  Bottom Layer w10: U5.2@1877.44,790 v1(1933,790)
NetR26_1: R26.1 U7.2 | length 70.8
  Bottom Layer w10: U7.2@1885,219.41 1885,245 1897.64,257.64 R26.1@1897.64,285
NetR30_1: R30.1 U8.2 | length 73.2
  Bottom Layer w10: U8.2@1705.04,219.41 1705.04,276.48 1712.64,276.48 R30.1@1712.64,285
NRST: C3.2 R4.1 S2.2 U1.14 | length 1763.5
  Top Layer w10: S2.2@212.2,870 341,870 v1(373,838) ; v1(1389,1197) 1389,1201 1417.69,1229.69 U1.14@1445.12,1229.69
  Bottom Layer w10: v1(373,838) 617.86,838 702.36,922.5 822,922.5 824,920.5 1012.44,920.5 1134.44,1042.5 1265.12,1042.5 1295.5,1072.88 1342.12,1072.88 1375,1040 1468,1040 1468,1184 1455,1197 1406,1197 1395,1208 ; v1(1389,1197) 1395,1203 1395,1208 ; C3.2@1445,1227.68 1419.32,1227.68 1419,1227.36 R4.1@1395,1227.36 1395,1208
OSC_IN: C5.2 U1.12 Y1.2 | length 555.1
  Top Layer w10: Y1.2@1341.26,775 1358.22,775 1425.96,842.74 1447.74,842.74 1482,877 1482,1160 1492,1170 ; U1.12@1445.12,1190.32 1479,1190.32 1479,1179 1488,1170 1492,1170 ; C5.2@1505,1170 1492,1170
OSC_OUT: C4.2 U1.13 Y1.1 | length 952.7
  Top Layer w10: U1.13@1445.12,1210 1499,1210 1505,1216 C4.2@1505,1230.36 1494.64,1230.36 1482,1243 1482,1289.61 1520.39,1289.61 1553,1257 1553,1175.5 1600,1128.5 1671.45,1128.5 1682,1117.95 1682,849.97 1607.03,775 Y1.1@1498.74,775
RF_CE: JP2.6 U1.52 | length 529.2
  Top Layer w10: U1.52@834.88,1426.54 858,1426.54 860.54,1424 1041.3,1424 1072,1454.7 v1(1075,1454.7) ; v1(1075,1575) 1140.74,1640.74 1140.74,1665.74 JP2.6@1150,1675
  Bottom Layer w10: v1(1075,1454.7) 1075,1476.56 1110,1511.56 1110,1535 v1@1075,1570
RF_CSN: JP2.3 U1.51 | length 1865.9
  Top Layer w10: v1(680,1488) 721.78,1446.22 U1.51@834.88,1446.22
  Bottom Layer w10: v1(680,1488) 677,1491 467,1491 409.57,1548.43 409.57,1599.57 426,1616 482,1616 512,1586 512,1563 543.5,1531.5 562.5,1531.5 587,1556 587,1644 772.92,1829.92 1151.54,1829.92 1274.92,1829.92 1290,1814.84 1290,1745.86 1279.22,1735.08 1189.92,1735.08 JP2.3@1150,1775
RF_MISO: JP2.8 U1.53 | length 2292.9
  Top Layer w10: v1(630,1461) 684.15,1406.85 U1.53@834.88,1406.85
  Bottom Layer w10: v1(630,1461) 618.05,1472.95 432.33,1472.95 394.57,1510.71 394.57,1761.13 416,1782.57 469.57,1782.57 575,1888 575,1930 608,1963 1407,1963 1500,1870 1500,1740 1435,1675 JP2.8@1350,1675
RF_MOSI: JP2.2 U1.54 | length 1383.7
  Top Layer w10: U1.54@834.88,1387.17 1050.17,1387.17 v1(1101,1438)
  Bottom Layer w10: v1(1101,1438) 1095.2,1432.2 1065.68,1432.2 1052.5,1445.38 1052.5,1595.53 1027.95,1620.08 1027.25,1620.08 951.33,1696 806,1696 774,1728 774,1776 784,1786 981.16,1786 1010.08,1814.92 1110.08,1814.92 1210.08,1814.92 JP2.2@1250,1775
RF_SCK: JP2.7 U1.47 | length 1273.2
  Top Layer w10: U1.47@962.83,1515.12 962.83,1544 966.33,1547.5 969.32,1547.5 974.51,1552.69 1019.51,1552.69 1037.5,1570.68 1037.5,1602.5 1010.08,1629.92 1010.08,1885.08 1035,1910 v1@1244.14,1910
  Bottom Layer w10: v1(1246.21,1910) 1405,1910 1460,1855 1460,1740 1434.92,1714.92 1304.92,1714.92 1279.26,1689.26 1277.75,1689.26 1263.49,1675 JP2.7@1250,1675
STDBY_LED: R29.2 U5.6 | length 163.5
  Bottom Layer w10: R29.2@1520,742.36 1600,742.36 1602.36,740 U5.6@1682.56,740
STDBY_LED_1: R33.2 U6.6 | length 195.2
  Top Layer w10: R33.2@1537.64,485 1537,485 1537,512 1564,539 v1(1608,539)
  Bottom Layer w10: v1(1608,539) 1639,539 1653,525 U6.6@1687.56,525
SWCLK: JP1.3 U1.76 | length 1999.2
  Top Layer w10: v1(903,1473) 907.2,1477.2 1093.62,1477.2 1123.5,1447.32 1123.5,1096.68 980.32,953.5 926.76,953.5 903.78,930.53 U1.76@903.78,904.88
  Bottom Layer w10: JP1.3@535,1915 445,1825 412,1825 379,1792 379,1494.95 416,1457.95 480.05,1457.95 500,1438 648,1438 672,1462 695,1462 736,1503 888,1503 903,1488 v1(903,1473)
SWDIO: JP1.1 U1.72 | length 1340.4
  Top Layer w10: v1(764,1018) 778.84,1032.84 U1.72@834.88,1032.84
  Bottom Layer w10: JP1.1@335,1915 335,1344 384.44,1294.56 559.36,1294.56 614.5,1239.42 614.5,1020.26 616.76,1018 v1(764,1018)
TOUCH_CS: P1.4 U1.36 | length 2492.8
  Top Layer w10: U1.36@1179.37,1515.12 1178.07,1516.42 1178.07,1547.83 1171.51,1554.39 1171.51,1614.29 1195.08,1637.85 1195.08,1697.75 1232.41,1735.08 1266.54,1735.08 1289.92,1758.46 1289.92,1835.88 1280,1845.8 1280,1923.22 1295.78,1939 2064,1939 2081,1922 2081,1403 2048,1370 1984,1370 1965.47,1351.47 1965.47,869.53 P1.4@2005,830
TOUCH_INT: P1.1 U1.33 | length 2102.4
  Top Layer w10: U1.33@1238.43,1515.12 1239.73,1516.42 1239.73,1537.51 1241.81,1539.6 1241.81,1542.88 1255,1556.07 1255,1629.22 1260.86,1635.08 1365.86,1635.08 1369.52,1638.74 1433.74,1638.74 1484.5,1689.5 1529.5,1689.5 1553,1666 1553,1463.58 1788.42,1463.58 1812,1440 1812,1255 1792,1235 1760,1235 1713.5,1188.5 1713.5,960.5 1824,850 1824,562 1856,530 P1.1@2005,530
TOUCH_MISO: P1.2 U1.31 | length 1976.1
  Top Layer w10: U1.31@1277.8,1515.12 1277.8,1554.17 1270,1561.97 1270,1609.14 1275.86,1615 1309.54,1615 1314.54,1620 1371.99,1620 1375.73,1623.74 1406.8,1623.74 1422.67,1607.87 1447.13,1607.87 v1(1450,1605)
  Bottom Layer w10: v1(1450,1605) 1832,1605 1853.5,1626.5 1920,1626.5 1943,1603.5 1943,1521 1984,1480 2021,1480 2045,1456 2045,1301 2016.5,1272.5 1968.5,1272.5 1965,1269 1965,1189 1984,1170 2027,1170 2045,1152 2045,670 P1.2@2005,630
USB_DM: U1.70 U10.6 | length 1027
  Top Layer w10: v1(763,869) 763,976 741.5,997.5 741.5,1040.96 747.36,1046.82 764.12,1046.82 789.51,1072.21 U1.70@834.88,1072.21 ; v1(1136,540) 1152.6,523.4 U10.6@1152.6,494.41
  Bottom Layer w10: v1(763,869) 763,565 788,540 v1(1136,540)
USB_DP: U1.71 U10.4 | length 1482
  Top Layer w10: v1(814,900) 854.23,900 872.48,918.25 872.48,941.65 930,999.17 930,1030.51 907.99,1052.52 U1.71@834.88,1052.52 ; U10.4@1227.4,494.41 1227.4,494 v1(1256,465.4)
  Bottom Layer w10: v1(814,900) 807,907 736,907 725,896 725,470 802.31,392.69 1216,392.69 1256,432.69 v1(1256,465.4)
VBAT: C15.2 R16.2 U1.6 | length 705.1
  Top Layer w10: v1(1403,1072.21) U1.6@1445.12,1072.21
  Bottom Layer w10: R16.2@850.59,980 907.79,980 922.79,995 958.18,995 975.68,1012.5 995.53,1012.5 1045.71,1062.68 1255.3,1062.68 1280.5,1087.88 1357.12,1087.88 1382.32,1062.68 1412.53,1062.68 ; v1(1403,1072.21) 1412.53,1062.68 ; C15.2@1445,1062.68 1412.53,1062.68
VCAP_1: C1.2 U1.49 | length 273.1
  Top Layer w10: U1.49@923.46,1515.12 923.46,1544 965,1585.54 v1(965,1590.27)
  Bottom Layer w10: C1.2@947.68,1450 925.5,1450 925.5,1495.95 923.19,1498.26 923.19,1533.19 965,1575 v1(965,1590.27)
VCAP_2: C2.2 U1.73 | length 552.3
  Top Layer w10: U1.73@834.88,1013.15 800,1013.15 791,1004.15 791,922.5 825.5,922.5 v1(846,943) ; v1(975,980) 980,985 v1(980,1050)
  Bottom Layer w10: C2.2@845,1069.65 877.35,1069.65 897,1050 v1(980,1050) ; v1(846,943) 850,947 896,947 929,980 v1(975,980)
VCCNRF: C25.1 C33.2 JP2.4 R24.2 U4.2 | length 3204.6
  Top Layer w10: U4.2@422,602 440,602 440,590 448,582 525,582 ; v1(531,1683) 500.5,1652.5 500.5,1306 454,1259.5 454,844 466,832 582,832 590,824 R24.2@590,810 ; R24.2@592.64,810 R24.2@590,810 ; C33.2@610,599.88 592.12,582 525,582 ; v1(1355,1852.42) 1355,1850 1445,1760 1568.5,1760 1595,1733.5 C25.1@1595,1733.43 ; 525,582 525,745.31 573,793.31 589.69,810 R24.2@590,810
  Bottom Layer w10: v1(531,1683) 581,1683 763,1865 1340,1865 1352.58,1852.42 v1(1355,1852.42) 1400,1807.42 1400,1740.86 1394.14,1735 1300.36,1735 1285.43,1720.08 1104.92,1720.08 JP2.4@1050,1775
VDD1: C8.2 C9.2 C10.2 C11.2 C12.2 C13.2 C14.2 C28.2 D4.2 J1.3 JP1.4 P2.4 R4.2 R11.2 R12.2 R13.2 R14.1 R16.1 R17.2 R18.2 R23.2 U1.11 U1.19 U1.28 U1.50 U1.75 U1.100 U3.2 | length 7415
  Top Layer w10: v1(553,1554) 553,1470.8 577.5,1446.3 v1(577.5,980) ; C28.2@629.88,230 629.88,307 642,319.12 642,373 ; D4.2@632.99,1505 656.3,1505 662.5,1511.2 701.3,1511.2 711,1501.5 711,1488 727,1472 820,1472 852,1504 852,1863 800,1915 ; JP1.4@635,1915 800,1915 ; U3.2@642,398 642,373 ; C13.2@709.82,955 709.82,956.26 v1(740,956.26) ; v1(814,945) 814,973.78 U1.75@834.88,973.78 ; U1.50@903.78,1515.12 903.78,1532 903,1532.78 903,1876 864,1915 ; v1(970,443) 922,395 896,395 ; J1.3@980,785 947,752 947,446 896,395 ; v1(1015,1580) 995.08,1599.92 995.08,1879.92 960,1915 864,1915 ; v1(1310,1430) 1311.95,1431.95 1326.95,1431.95 1336.85,1441.85 U1.28@1336.85,1515.12 ; v1(1379,1134) 1379,952 1376.22,949.22 U1.100@1376.22,904.88 1376.22,884 1387.5,872.72 v1(1435,872.72) ; U1.11@1445.12,1170.63 1428,1170.63 1426.63,1172 1412,1172 1409.5,1174.5 1376,1174.5 1366.5,1184 1366.5,1275.5 1419.11,1328.11 U1.19@1445.12,1328.11 1472,1328.11 v1(1488,1312.11) ; 642,373 848,373 848,395 R23.2@867.64,395 896,395 ; 800,1915 864,1915
  Bottom Layer w10: v1(553,1554) 553,1586 508,1631 508,1788 JP1.4@635,1915 ; v1(577.5,980) R16.1@799.41,980 ; v1(740,956.26) 795.67,956.26 799.41,960 R16.1@799.41,980 ; C11.2@810,1069.64 787,1069.64 787,1013 799.41,1000.59 R16.1@799.41,980 ; v1(814,945) 814,980 R16.1@799.41,980 ; C8.2@945,1515 951.81,1521.81 951.81,1527.53 v1@1004.28,1580 ; v1(970,443) 1093.27,443 1186.34,536.07 P2.4@1186.34,619.84 ; J1.3@980,785 1049.51,715.49 1200.49,715.49 1270,785 R17.2@1270,787.64 R18.2@1320,787.64 R11.2@1370,787.64 R12.2@1420,787.64 ; v1(1015,1580) v1@1004.28,1580 ; 1265,1484 1265,1435.86 1270.86,1430 v1(1310,1430) ; C14.2@1282.52,1515.12 1282.52,1496 1287.73,1490.8 1287.73,1485.59 ; v1(1379,1134) 1379,1152 1396.64,1169.64 ; R4.2@1395,1272.64 1395,1253 1376,1253 1365,1242 1366.66,1169.64 1396.64,1169.64 ; v1(1435,872.72) 1420,857.72 R12.2@1420,787.64 ; C10.2@1445,1167.32 1428.32,1167.32 1426,1169.64 C9.2@1410,1169.64 1396.64,1169.64 ; C12.2@1445,1340 1460.11,1340 ; R13.2@1470,787.64 R12.2@1420,787.64 ; v1(1488,1312.11) 1460.11,1340 ; v1@1004.28,1580 1004.28,1434.72 1024,1415 1196,1415 1266.59,1485.59 1287.73,1485.59 ; 1287.73,1485.59 R14.1@1385,1485.59 1417.59,1485.59 1426.13,1494.13 1462.87,1494.13 1493,1464 1493,1360 1473,1340 1460.11,1340
  other v1: 1365,1253
VDDA: C7.1 C30.1 U1.22 | length 1302.2
  Top Layer w10: v1(1361,1371) 1377.17,1387.17 U1.22@1445.12,1387.17 ; C30.1@1840,1683.9 1840,1628 1856,1612 1882,1612 1890,1604 v1(1890,1588)
  Bottom Layer w10: v1(1361,1371) 1362.32,1372.32 C7.1@1390,1372.32 1413,1372.32 1413,1321.21 1444.6,1289.61 1465.39,1289.61 1612,1143 1856,1143 1890,1177 v1(1890,1588)
VREF+: C6.2 C27.1 R14.2 U1.21 | length 1039.9
  Top Layer w10: v1(1355.66,1429.5) 1347.97,1429.5 1342.11,1423.64 1339.86,1423.64 1338.5,1422.29 1338.5,1360 1350,1348.5 1379.5,1348.5 1398.48,1367.48 U1.21@1445.12,1367.48 1478.52,1367.48 1568,1278 1568,1225.5 1598.5,1195 1598.5,1161 1616,1143.5 1688,1143.5 1697,1134.5 1697,951 1750,898 C27.1@1750,810
  Bottom Layer w10: v1(1355.66,1429.5) 1380.09,1429.5 R14.2@1385,1434.41 1413,1434.41 1416.27,1437.68 C6.2@1445,1437.68
pads on no net: J2.A2 J2.A3 J2.A5 J2.A8 J2.A10 J2.A11 J2.B2 J2.B3 J2.B5 J2.B8 J2.B10 J2.B11 J2.M JP2.1 JP3.5 JP4.5 P1.6 P2. P2.9 U1.1 U1.2 U1.3 U1.4 U1.5 U1.7 U1.8 U1.9 U1.15 U1.16 U1.17 U1.18 U1.23 U1.38 U1.39 U1.40 U1.41 U1.42 U1.43 U1.44 U1.45 U1.46 U1.48 U1.55 U1.56 U1.57 U1.58 U1.63 U1.65 U1.66 U1.69 U1.77 U1.82 U1.83 U1.84 U1.85 U1.86 U1.87 U1.88 U1.89 U1.90 U1.91 U1.93 U1.95 U1.96 U1.97 U1.98 U7.4 U8.4 U.9 U.10 U.14 U.16
copper on no net:
  other v3: 61.3,1333.78 61.3,1806.22

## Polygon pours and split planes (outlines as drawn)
GND on Bottom Layer "GND_L02_P001" (solid, pour order 1): 0,0 2335,0 2340,5 2335,10 2335,2060 0,2060
GND on Top Layer "GND_L01_P000" (solid, pour order 0): 5,5 10,0 2335,0 2335,2060 0,2060

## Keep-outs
Keep-Out Layer:
  lines w10: 0,0 0,2060 2335,2060 2335,0 ; 5,5 2340,5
